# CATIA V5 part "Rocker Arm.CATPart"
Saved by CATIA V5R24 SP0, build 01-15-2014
Part number: Rocker Arm
Bounding box of the stored display mesh (mm): x -80 to 90, y -46.2 to 35, z -20 to 20
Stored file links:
  E:\Desktop_RNH\학부 CAD 수업 자료\[CAD_V2]강의자료(CAD)_2017년 이후\툴바예제\DMU Kinematics_2017\Example\Rocker Arm.CATPart

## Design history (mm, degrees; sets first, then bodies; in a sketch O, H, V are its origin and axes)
Body1 (main body)
  Sketch1 on xy-plane, origin (0, 0, 0), H (1, 0, 0), V (0, 1, 0)
    line L1 (78.3761, 12.6851) -> (36.3856, 22.3849)
    line L2 (90, -1.93) -> (90, -6.0902)
    line L3 (71.1198, -26.0588) -> (30.3575, -28.3447)
    line L4 (-80, 2.4322) -> (-80, -20)
    line L5 (-43.6841, -21.723) -> (-29.6164, -25.5608)
    line L6 (-72.7169, 12.0561) -> (-33.5886, 23.1023)
    arc A1 centre (0, 0) radius 35 from (18.3805, 29.7852) to (-18.3805, 29.7852) ccw
    point P1 (0, 35)
    arc A2 centre (33.1571, -78.2663) radius 50 from (30.3575, -28.3447) to (13.6529, -32.2273) ccw
    arc A3 centre (49.89, 80.8454) radius 60 from (36.3856, 22.3849) to (18.3805, 29.7852) cw
    arc A4 centre (-49.89, 80.8454) radius 60 from (-18.3805, 29.7852) to (-33.5886, 23.1023) cw
    arc A5 centre (0, 0) radius 35 from (-16.7291, -30.7431) to (13.6529, -32.2273) ccw
    point P11 (0, -35)
    arc A6 centre (-45.4077, -83.4455) radius 60 from (-16.7291, -30.7431) to (-29.6164, -25.5608) ccw
    arc A7 centre (75, -1.93) radius 15 from (78.3761, 12.6851) to (90, -1.93) cw
    arc A8 centre (-70, 2.4322) radius 10 from (-72.7169, 12.0561) to (-80, 2.4322) ccw
    arc A9 centre (-45, -26.5468) radius 5 from (-50, -26.5468) to (-43.6841, -21.723) cw
    point P21 (-50, -26.5468)
    point P24 (-80, -20)
    spline S1 through (-80, -20) (-79, -32) (-73, -44) (-60, -45) (-51, -33) (-50, -26.5468)
    arc A10 centre (70, -6.0902) radius 20 from (90, -6.0902) to (71.1198, -26.0588) cw
    point P28 (-80, -20)
    point P29 (-50, -26.5468)
    radius A7 = 15
    radius A8 = 10
    radius A9 = 5
    radius A10 = 20
    vertical: L4 V
    tangency: A2 L3, A3 L1, A3 A1, A4 A1, A4 L6, A5 A2, A6 A5, A6 L5, A7 L1, A7 L2, A8 L6, A8 L4, A9 L5, A10 L2, A10 L3
    coincidence: P28 P24, P29 P21
  Pad1: profile Sketch1, direction (0, 0, 1), length 15
  Sketch2 on end face of Pad1, origin (0, 0, 15), H (1, 0, 0), V (0, 1, 0)
  Pocket1: profile Sketch2, direction (0, 0, -1), length 5
  Sketch3 on end face of Pocket1, origin (0, 0, 10), H (1, 0, 0), V (0, 1, 0)
    circle A1 centre (0, 0) radius 30.0167
  Pad2: profile Sketch3, direction (0, 0, 1), length 10
  Fillet1: radius 5, on edge [end face of Pocket1 | face of Pad2 from Sketch3.A1] (x2)
  Chamfer1: length 3, angle 45, on end face of Pad2
  Sketch4 on end face of Pad2, origin (0, 0, 20), H (1, 0, 0), V (0, 1, 0)
    circle A1 centre (0, 0) radius 20
    point P1 (20, 0)
    coincidence: A1 P1, P1 H
  Pocket2: profile Sketch4, direction (0, 0, -1), through (limit type 3)
  Chamfer2: length 1, angle 45, on edge [end face of Pad2 | face of Pocket2 from Sketch4.A1]
  Mirror1: of the body so far, about xy-plane
  DatumCurve1
  Sketch5 on xy-plane, origin (0, 0, 0), H (1, 0, 0), V (0, 1, 0)
    point P1 (-70.2035, -45.4708)
  Sketch6 on xy-plane, origin (0, 0, 0), H (1, 0, 0), V (0, 1, 0)
    point P1 (73.473, -25.7863)
  Plane1: type Tangent, Support face of Pad1, RefPoint Sketch5
  Plane2: type Tangent, Support face of Pad1, RefPoint Sketch6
